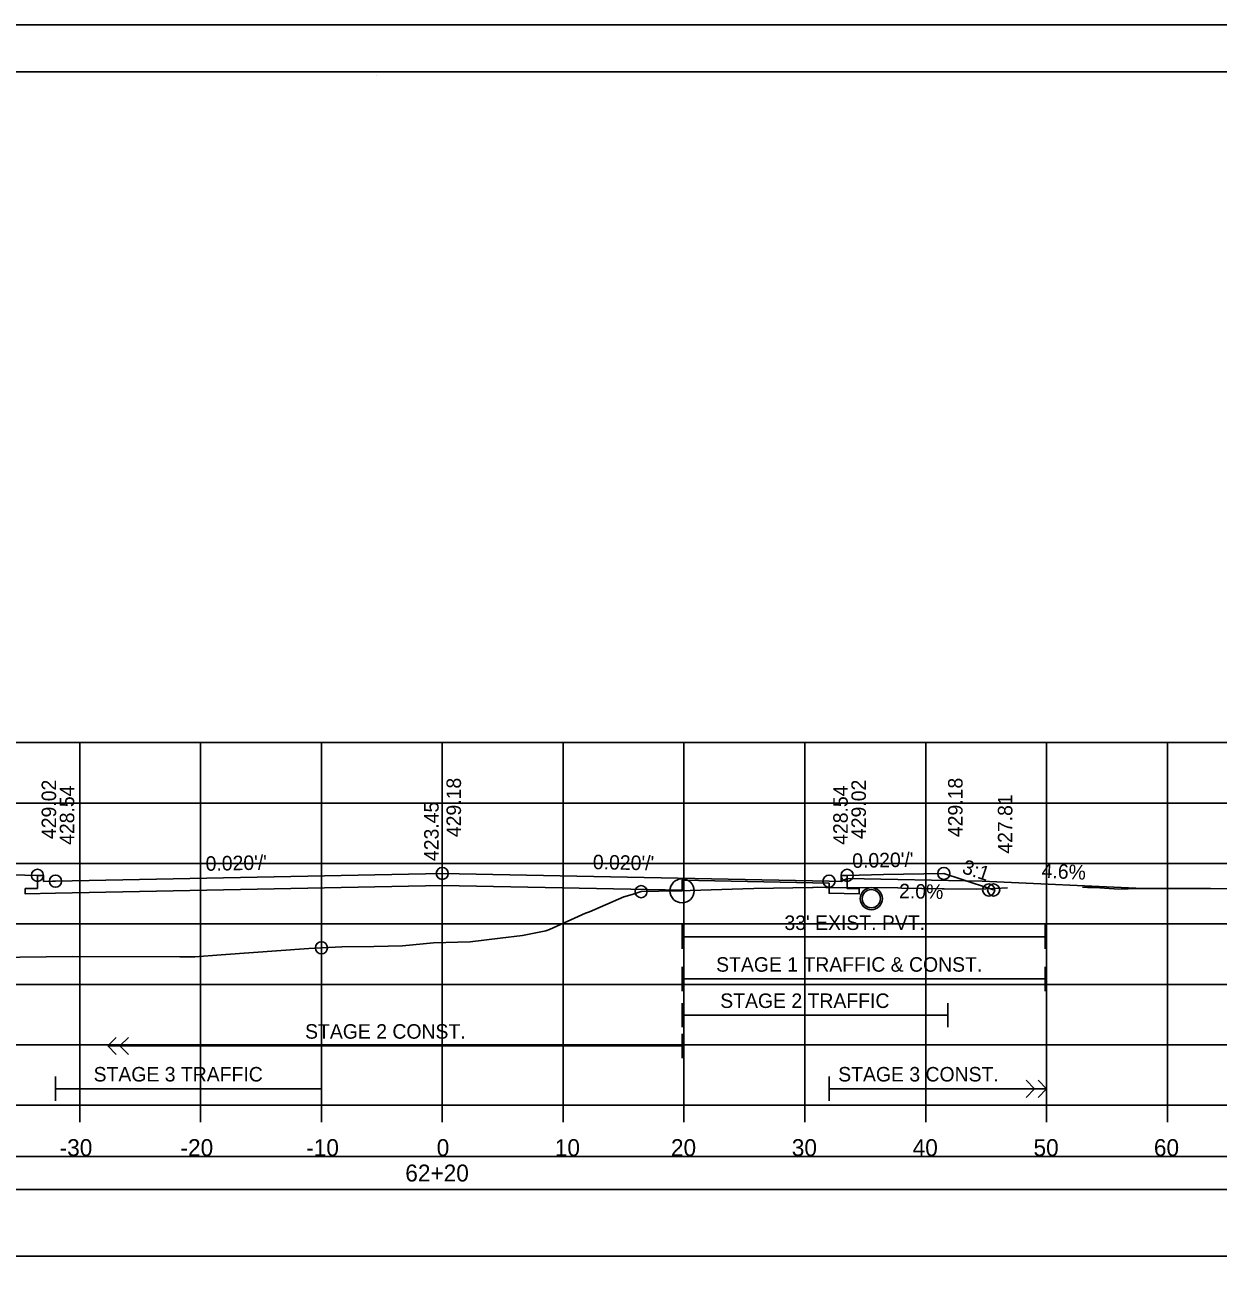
# Model space of a CAD drawing. Extents: x 1371057 to 1372761, y 380005 to 390517.
# Drawn here: x 1371526.3 to 1371625.1, y 385022.4 to 385125.2 of the extents above; entities that cross this region are included whole.
import ezdxf

# ---------------------------------------------------------------- set-up
doc = ezdxf.new("R2010")
doc.units = 0
for name, color, linetype in [('R_Alt Surface', 7, 'Continuous'), ('R_Axis', 7, 'Continuous'), ('R_Axis Annot', 7, 'Continuous'), ('R_Border', 7, 'Continuous'), ('R_Detour', 7, 'Continuous'), ('R_Dimension', 7, 'Continuous'), ('R_Drive', 7, 'Continuous'), ('R_Exist Surface', 7, 'Continuous'), ('R_Fin Surface', 7, 'Continuous'), ('R_Grid', 7, 'Continuous'), ('R_No Plot', 7, 'Continuous'), ('R_Striping', 7, 'Continuous'), ('R_Water', 7, 'Continuous'), ('R_Xsect Elev', 7, 'Continuous'), ('R_Xsect Slope', 7, 'Continuous')]:
    doc.layers.add(name, color=color, linetype=linetype)

msp = doc.modelspace()

# ---------------------------------------------------------------- linework, layer by layer
at = {"layer": 'R_Alt Surface'}
for points in [[(1371594.37, 385054.85), (1371594.37, 385053.77), (1371595.37, 385053.75), (1371595.37, 385053.32), (1371592.87, 385053.37), (1371592.87, 385053.37), (1371592.87, 385054.2), (1371580.71, 385054.45), (1371580.71, 385053.62), (1371560.87, 385054.01), (1371528.87, 385053.37), (1371526.37, 385053.32), (1371526.37, 385053.75), (1371527.37, 385053.77), (1371527.37, 385054.85)], [(1371580.71, 385050.76), (1371580.71, 385048.76)], [(1371610.75, 385050.76), (1371610.75, 385048.76)], [(1371580.71, 385049.76), (1371610.75, 385049.76)]]:
    msp.add_lwpolyline(points, dxfattribs=at)
at = {"layer": 'R_Axis'}
for p, q in [((1371410.87, 385035.83), (1371710.87, 385035.83)), ((1371530.87, 385034.43), (1371530.87, 385035.83)), ((1371540.87, 385034.43), (1371540.87, 385035.83)), ((1371550.87, 385034.43), (1371550.87, 385035.83)), ((1371560.87, 385034.43), (1371560.87, 385035.83)), ((1371570.87, 385034.43), (1371570.87, 385035.83)), ((1371580.87, 385034.43), (1371580.87, 385035.83)), ((1371590.87, 385034.43), (1371590.87, 385035.83)), ((1371600.87, 385034.43), (1371600.87, 385035.83)), ((1371610.87, 385034.43), (1371610.87, 385035.83)), ((1371620.87, 385034.43), (1371620.87, 385035.83))]:
    msp.add_line(p, q, dxfattribs=at)
at = {"layer": 'R_Border'}
for p, q in [((1371402.87, 385121.29), (1371719.05, 385121.29)), ((1371555.39, 385121.03), (1371555.39, 385121.03)), ((1371555.39, 385121.03), (1371555.39, 385121.03))]:
    msp.add_line(p, q, dxfattribs=at)
at = {"layer": 'R_Detour'}
msp.add_lwpolyline([(1371407.72, 385028.88), (1371714.03, 385028.88), (1371714.03, 385031.59), (1371407.72, 385031.59)], close=True, dxfattribs=at)
at = {"layer": 'R_Dimension'}
msp.add_lwpolyline([(1371407.72, 385023.36), (1371714.03, 385023.36), (1371714.03, 385028.88), (1371407.72, 385028.88)], close=True, dxfattribs=at)
at = {"layer": 'R_Drive'}
for p, q in [((1371593.87, 385054.35), (1371594.37, 385054.6)), ((1371594.37, 385054.6), (1371605.54, 385054.38)), ((1371618.87, 385053.77), (1371605.54, 385054.38))]:
    msp.add_line(p, q, dxfattribs=at)
at = {"layer": 'R_Exist Surface'}
for points in [[(1371519.3, 385048), (1371530.29, 385048.13), (1371539.15, 385048.12), (1371540.39, 385048.11), (1371542.58, 385048.27), (1371549.83, 385048.8), (1371552.57, 385048.94), (1371555.21, 385048.97), (1371557.57, 385049.01), (1371560.15, 385049.27), (1371563.19, 385049.35), (1371565.65, 385049.64), (1371567.5, 385049.87), (1371569.44, 385050.27), (1371569.73, 385050.36), (1371572.71, 385051.71), (1371573.04, 385051.84), (1371575.88, 385053.08), (1371576.58, 385053.27), (1371577.32, 385053.5), (1371580.25, 385053.57), (1371580.71, 385053.57), (1371581.39, 385053.59), (1371585.73, 385053.74), (1371586.66, 385053.76), (1371591.5, 385053.85), (1371591.57, 385053.85), (1371591.92, 385053.86), (1371592.61, 385053.85), (1371598.55, 385053.81), (1371598.86, 385053.8), (1371602.22, 385053.74), (1371602.39, 385053.74), (1371605.06, 385053.71), (1371606.63, 385053.75), (1371607.64, 385053.82)], [(1371613.85, 385053.86), (1371614.27, 385053.85), (1371614.87, 385053.84), (1371615.67, 385053.79), (1371616.84, 385053.71), (1371618.38, 385053.77), (1371622.08, 385053.75), (1371624.42, 385053.75), (1371627.03, 385053.73)]]:
    msp.add_lwpolyline(points, dxfattribs=at)
at = {"layer": 'R_Fin Surface'}
msp.add_lwpolyline([(1371498.72, 385048.13), (1371519.37, 385055.01), (1371519.37, 385055.01), (1371523.37, 385054.93), (1371524.37, 385054.91), (1371525.28, 385054.89), (1371527.37, 385054.85), (1371527.6, 385054.85), (1371527.87, 385054.85), (1371527.87, 385054.61), (1371527.88, 385054.35), (1371528.62, 385054.37), (1371528.87, 385054.37), (1371560.87, 385055.01), (1371560.88, 385055.01), (1371592.87, 385054.37), (1371593.87, 385054.35), (1371593.87, 385054.85), (1371594.01, 385054.85), (1371594.37, 385054.85), (1371597.37, 385054.91), (1371602.37, 385055.01), (1371603.79, 385054.54), (1371606.49, 385053.64)], dxfattribs=at)
at = {"layer": 'R_Grid'}
for p, q in [((1371410.87, 385065.83), (1371710.87, 385065.83)), ((1371530.87, 385035.83), (1371530.87, 385065.83)), ((1371540.87, 385035.83), (1371540.87, 385065.83)), ((1371550.87, 385035.83), (1371550.87, 385065.83)), ((1371560.87, 385035.83), (1371560.87, 385065.83)), ((1371570.87, 385035.83), (1371570.87, 385065.83)), ((1371580.87, 385035.83), (1371580.87, 385065.83)), ((1371590.87, 385035.83), (1371590.87, 385065.83)), ((1371600.87, 385035.83), (1371600.87, 385065.83)), ((1371610.87, 385035.83), (1371610.87, 385065.83)), ((1371620.87, 385035.83), (1371620.87, 385065.83)), ((1371410.87, 385060.83), (1371710.87, 385060.83)), ((1371410.87, 385055.83), (1371710.87, 385055.83)), ((1371410.87, 385050.83), (1371710.87, 385050.83)), ((1371410.87, 385045.83), (1371710.87, 385045.83)), ((1371410.87, 385040.83), (1371710.87, 385040.83)), ((1371410.87, 385035.83), (1371710.87, 385035.83))]:
    msp.add_line(p, q, dxfattribs=at)
at = {"layer": 'R_No Plot'}
msp.add_line((1371390.47, 385125.19), (1371723.8, 385125.19), dxfattribs=at)
for points in [[(1371390.46, 385125.19), (1371723.8, 385125.19), (1371723.8, 384911.85), (1371390.46, 384911.85)], [(1371636.79, 385121.29), (1371656.41, 385121.29), (1371656.41, 385111.41), (1371672.52, 385111.41), (1371695.72, 385111.41), (1371695.84, 385083.26), (1371719.05, 385083.26), (1371719.05, 384915.83), (1371402.87, 384915.83), (1371402.87, 385121.29)]]:
    msp.add_lwpolyline(points, close=True, dxfattribs=at)
for centre, radius in [((1371527.37, 385054.85), 0.5), ((1371560.87, 385055.01), 0.5), ((1371594.37, 385054.85), 0.5), ((1371602.37, 385055.01), 0.5), ((1371528.87, 385054.37), 0.5), ((1371580.71, 385053.57), 1), ((1371592.87, 385054.37), 0.5), ((1371577.32, 385053.5), 0.5), ((1371596.37, 385052.92), 0.917), ((1371606.08, 385053.64), 0.5), ((1371606.49, 385053.64), 0.5), ((1371550.87, 385048.86), 0.5)]:
    msp.add_circle(centre, radius, dxfattribs=at)
at = {"layer": 'R_Striping'}
for p, q in [((1371580.71, 385047.28), (1371580.71, 385045.28)), ((1371610.75, 385047.28), (1371610.75, 385045.28)), ((1371580.71, 385046.28), (1371610.75, 385046.28)), ((1371580.71, 385044.28), (1371580.71, 385042.28)), ((1371602.71, 385044.28), (1371602.71, 385042.28)), ((1371580.71, 385043.28), (1371602.71, 385043.28)), ((1371533.19, 385040.74), (1371533.9, 385041.45)), ((1371534.19, 385040.74), (1371534.9, 385041.45)), ((1371580.71, 385041.74), (1371580.71, 385039.74)), ((1371533.19, 385040.74), (1371580.71, 385040.74)), ((1371533.9, 385040.03), (1371533.19, 385040.74)), ((1371534.9, 385040.03), (1371534.19, 385040.74)), ((1371528.87, 385038.2), (1371528.87, 385036.2)), ((1371550.87, 385038.2), (1371550.87, 385036.2)), ((1371592.87, 385038.2), (1371592.87, 385036.2)), ((1371609.87, 385037.2), (1371609.17, 385037.9)), ((1371610.87, 385037.2), (1371610.17, 385037.9)), ((1371550.87, 385037.2), (1371528.87, 385037.2)), ((1371592.87, 385037.2), (1371610.87, 385037.2)), ((1371609.17, 385036.49), (1371609.87, 385037.2)), ((1371610.17, 385036.49), (1371610.87, 385037.2))]:
    msp.add_line(p, q, dxfattribs=at)
at = {"layer": 'R_Water'}
msp.add_circle((1371596.37, 385052.92), 0.75, dxfattribs=at)
at = {"layer": 'R_Xsect Elev'}
msp.add_line((1371560.87, 385049.29), (1371560.87, 385063.03), dxfattribs=at)

# ---------------------------------------------------------------- texts
at = {"layer": 'R_Axis Annot'}
for s, p in [('-30', (1371529.21, 385031.63)), ('-20', (1371539.21, 385031.63)), ('-10', (1371549.61, 385031.63)), ('0', (1371560.41, 385031.63)), ('10', (1371570.18, 385031.63)), ('20', (1371579.79, 385031.63)), ('30', (1371589.79, 385031.63)), ('40', (1371599.79, 385031.63)), ('50', (1371609.79, 385031.63)), ('60', (1371619.75, 385031.63)), ('62+20', (1371557.81, 385029.53))]:
    msp.add_text(s, height=1.4, dxfattribs=at).set_placement(p)
at = {"layer": 'R_Striping'}
for s, p in [('STAGE 1 TRAFFIC & CONST.', (1371583.53, 385046.88)), ('STAGE 2 TRAFFIC', (1371583.87, 385043.88)), ('STAGE 2 CONST.', (1371549.52, 385041.34)), ('STAGE 3 TRAFFIC', (1371532.02, 385037.8)), ('STAGE 3 CONST.', (1371593.63, 385037.8))]:
    msp.add_text(s, height=1.2, dxfattribs=at).set_placement(p)
at = {"layer": 'R_Water'}
msp.add_text("33' EXIST. PVT.", height=1.2, rotation=360, dxfattribs=at).set_placement((1371589.18, 385050.33))
at = {"layer": 'R_Xsect Elev'}
for s, rotation, p in [('429.02', 90, (1371528.92, 385057.85)), ('429.18', 90, (1371562.42, 385058.01)), ('429.02', 90, (1371595.92, 385057.85)), ('429.18', 90, (1371603.92, 385058.01)), ('428.54', 90, (1371530.42, 385057.37)), ('428.54', 90, (1371594.42, 385057.37)), ('427.81', 90, (1371608.04, 385056.64)), ('423.45', 90, (1371560.57, 385056.03)), ('4.6%', 357.3663, (1371610.44, 385054.65)), ('2.0%', 358.8542, (1371598.66, 385052.96))]:
    msp.add_text(s, height=1.2, rotation=rotation, dxfattribs=at).set_placement(p)
at = {"layer": 'R_Xsect Slope'}
for s, rotation, p in [("0.020'/'", 1.1458, (1371541.3, 385055.22)), ("0.020'/'", 358.8542, (1371573.32, 385055.36)), ("0.020'/'", 1.1458, (1371594.8, 385055.46)), ('3:1', 341.5692, (1371603.8, 385055.06))]:
    msp.add_text(s, height=1.2, rotation=rotation, dxfattribs=at).set_placement(p)

doc.saveas('drawing.dxf')
